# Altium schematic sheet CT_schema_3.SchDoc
size 328 x 327 mm
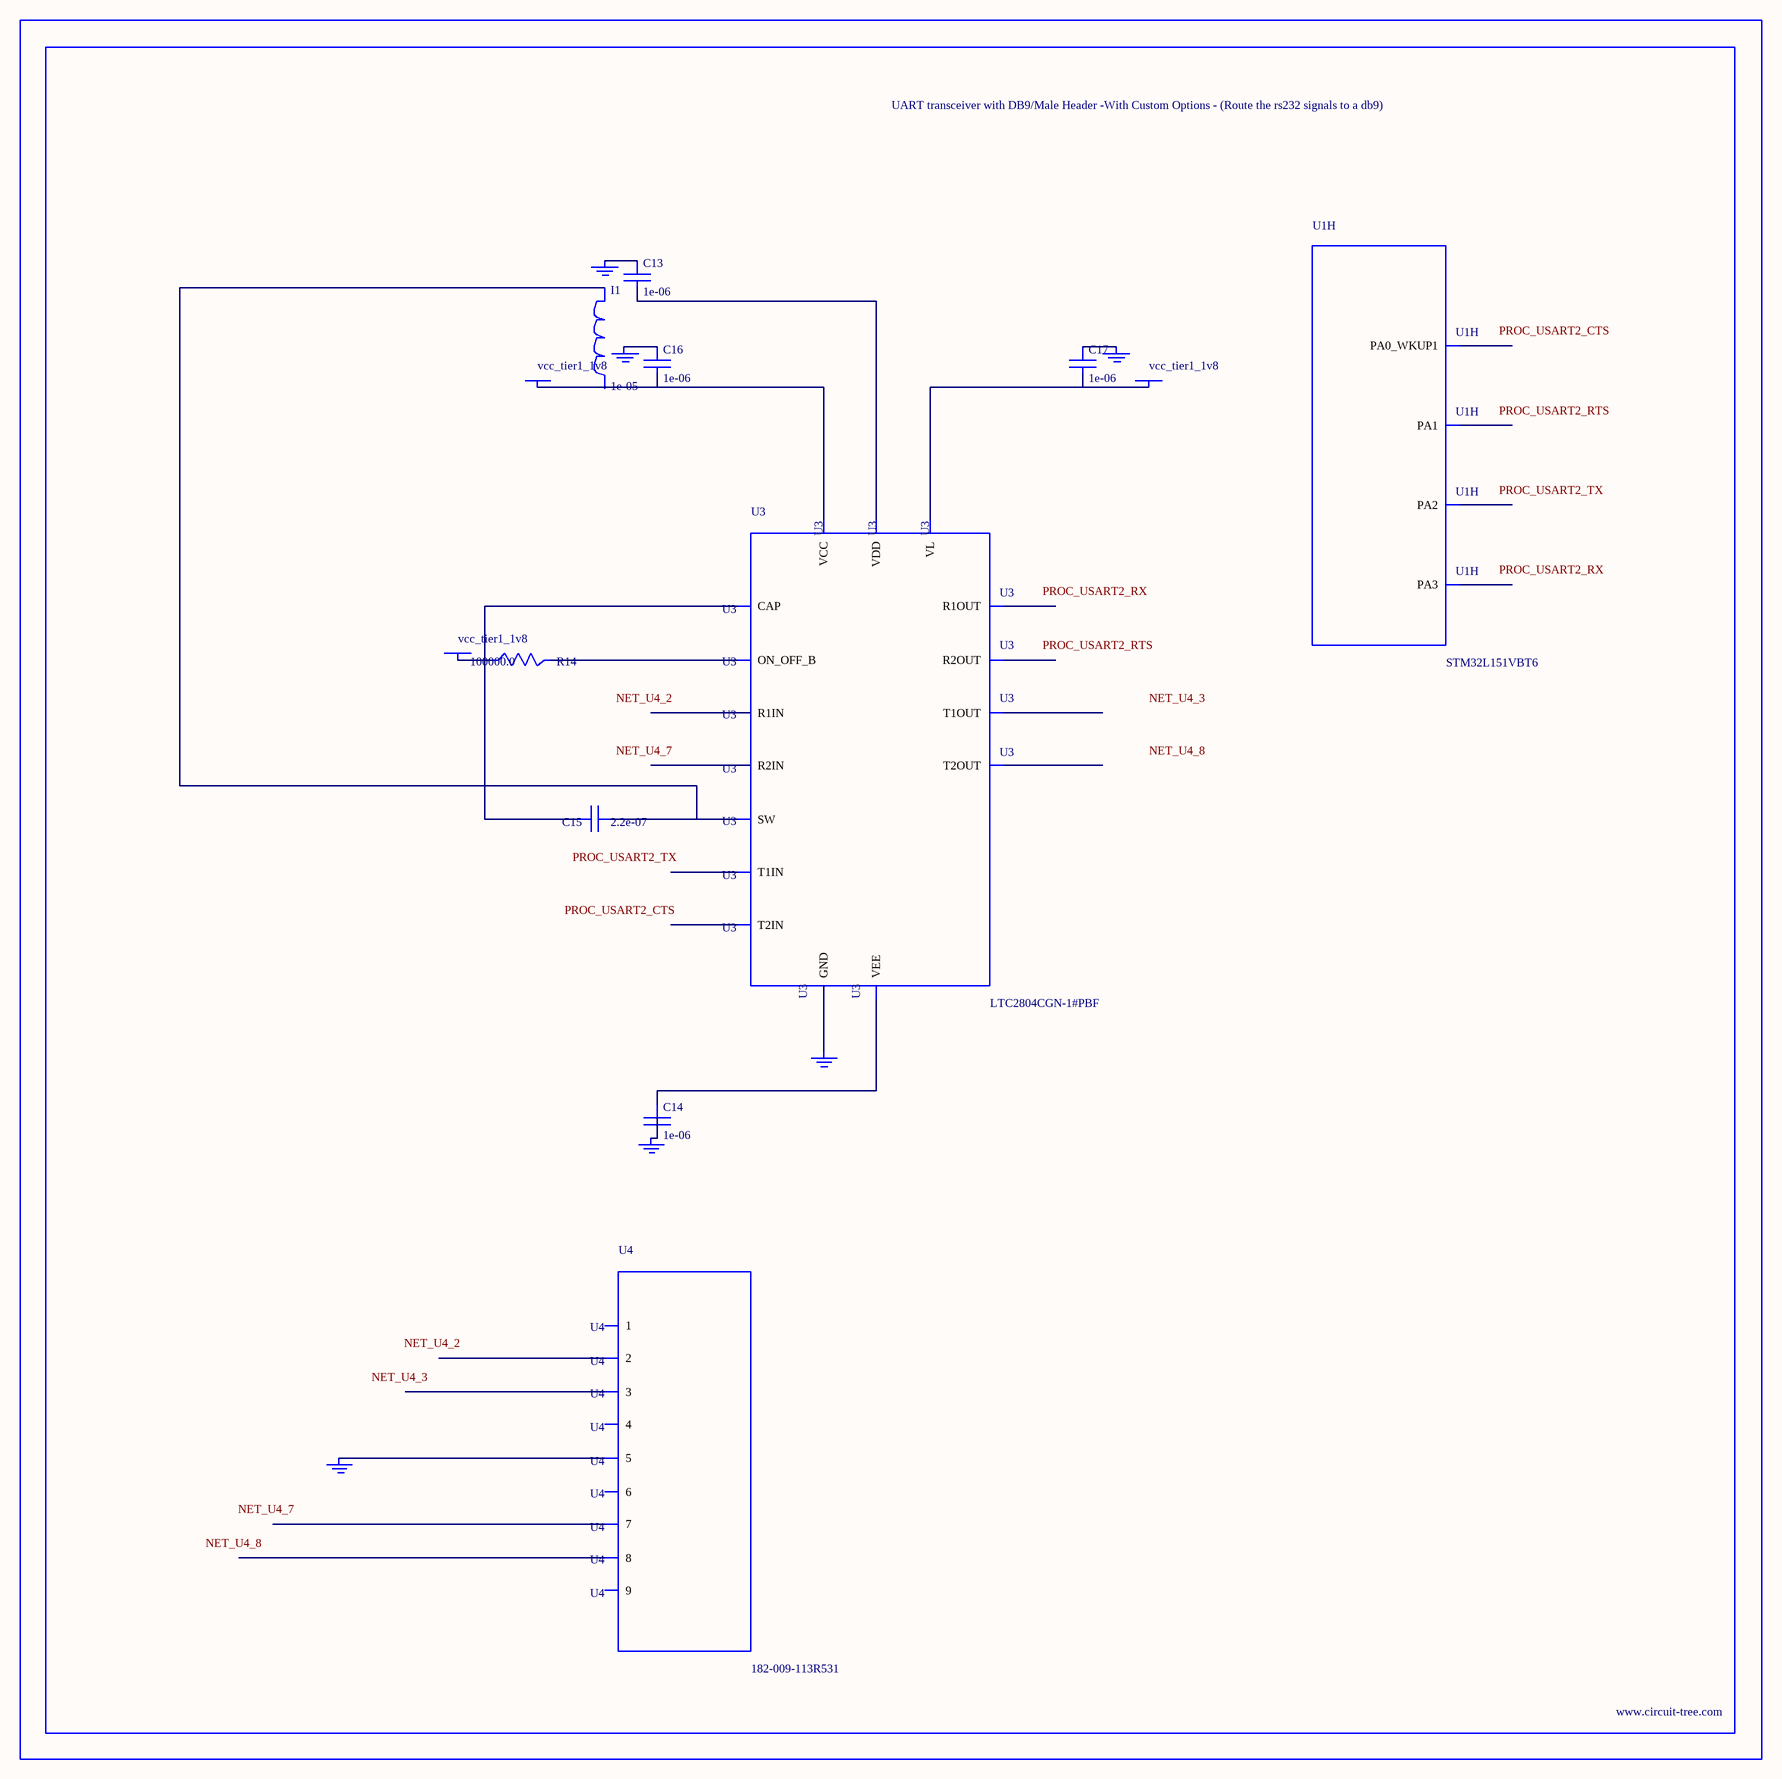
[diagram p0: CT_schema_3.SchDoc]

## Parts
BORDER2  (no value)
C13  1e-06  [C0603]
C14  1e-06  [C0603]
C15  2.2e-07  [C0603]
C16  1e-06  [C0603]
C17  1e-06  [C0603]
GND_INSTANCE_2_0  (no value)
GND_INSTANCE_2_1  (no value)
GND_INSTANCE_2_2  (no value)
GND_INSTANCE_2_3  (no value)
GND_INSTANCE_2_4  (no value)
GND_INSTANCE_2_5  (no value)
I1  1e-05  [L1210]
POWER_INSTANCE_2_0  vcc_tier1_1v8
POWER_INSTANCE_2_1  vcc_tier1_1v8
POWER_INSTANCE_2_2  vcc_tier1_1v8
R14  100000.0  [R0603]
U1  STM32L151VBT6  [LQFP100]  (part H of 11)
U3  LTC2804CGN-1#PBF  [SSOP-16]
U4  182-009-113R531  [182-009-MALE]

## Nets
NetC13_1: C13.1 GND_INSTANCE_2_1.0(GND)
NetC13_2: C13.2 U3.6(VDD)
NetC14_1: C14.1 U3.9(VEE)
NetC14_2: C14.2 GND_INSTANCE_2_2.0(GND)
NetC15_1: C15.1 I1.1 U3.7(SW)
NetC15_2: C15.2 U3.10(CAP)
NetC16_1: C16.1 GND_INSTANCE_2_0.0(GND)
NetC16_2: C16.2 POWER_INSTANCE_2_0.0(PWR) U3.5(VCC)
NetC17_1: C17.1 GND_INSTANCE_2_3.0(GND)
NetC17_2: C17.2 POWER_INSTANCE_2_2.0(PWR) U3.12(VL)
NetGND_INSTANCE_2_4_0: GND_INSTANCE_2_4.0(GND) U3.8(GND)
NetGND_INSTANCE_2_5_0: GND_INSTANCE_2_5.0(GND) U4.5
NetPOWER_INSTANCE_2_1_0: POWER_INSTANCE_2_1.0(PWR) R14.1
NetR14_2: R14.2 U3.11(ON_OFF_B)

Not connected (* = marked no-connect by the designer): I1 2; U1 23(PA0_WKUP1) 24(PA1) 25(PA2) 26(PA3); U3 1(R1IN) 2(R2IN) 3(T1OUT) 4(T2OUT) 13(T2IN) 14(T1IN) 15(R2OUT) 16(R1OUT); U4 1 2 3 4 6 7 8 9

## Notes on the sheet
- Labels drawn without touching a wire or pin: NET_U4_2, NET_U4_3, NET_U4_7, NET_U4_8, PROC_USART2_CTS, PROC_USART2_RTS, PROC_USART2_RX, PROC_USART2_TX

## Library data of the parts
BORDER2 = BORDER_PAGE2
C13 C14 C16 C17 = C0603C105K3RACTU
C15 = C0603C224K3RAC
GND_INSTANCE_2_0-GND_INSTANCE_2_5 = GND
I1 = CBC3225T100MR
POWER_INSTANCE_2_0-POWER_INSTANCE_2_2 = PWR
R14 = RC0603JR-07100KL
